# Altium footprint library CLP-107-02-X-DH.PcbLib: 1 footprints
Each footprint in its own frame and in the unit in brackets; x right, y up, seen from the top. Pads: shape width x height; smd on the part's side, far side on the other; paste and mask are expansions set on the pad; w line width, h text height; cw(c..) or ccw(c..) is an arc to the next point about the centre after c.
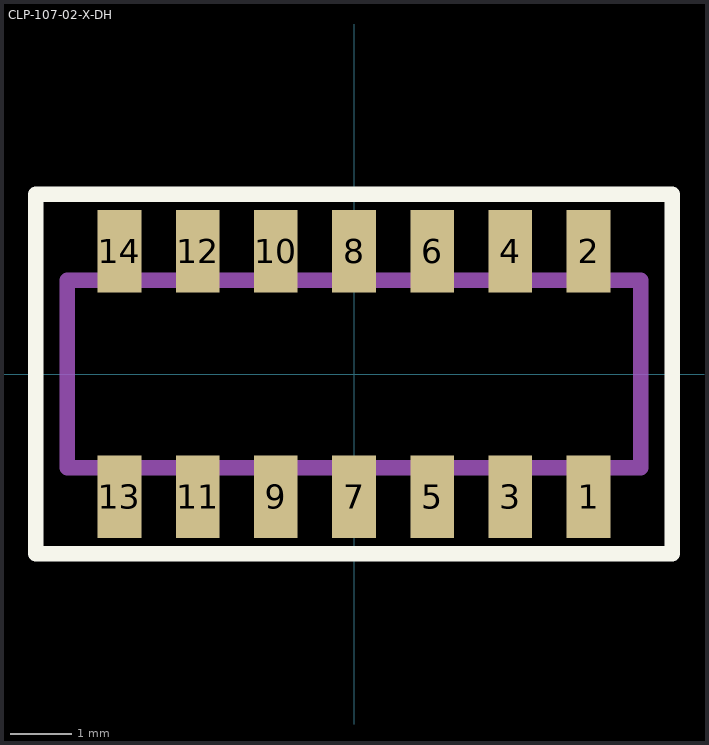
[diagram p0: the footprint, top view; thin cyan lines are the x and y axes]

## CLP-107-02-X-DH [mil]
pads (14):
  rect 28x53 smd mask+2: 1(150,-78.5) 2(150,78.5) 3(100,-78.5) 4(100,78.5) 5(50,-78.5) 6(50,78.5) 7(0,-78.5) 8(0,78.5) 9(-50,-78.5) 10(-50,78.5) 11(-100,-78.5) 12(-100,78.5) 13(-150,-78.5) 14(-150,78.5)
Top Overlay:
  lines w10: -203.5,-115 -203.5,115 203.5,115 203.5,-115 -203.5,-115
Mechanical 1:
  lines w10: -183.5,-60 -183.5,60 183.5,60 183.5,-60 -183.5,-60
  text "J1" at -17.57,-18 h30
